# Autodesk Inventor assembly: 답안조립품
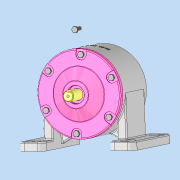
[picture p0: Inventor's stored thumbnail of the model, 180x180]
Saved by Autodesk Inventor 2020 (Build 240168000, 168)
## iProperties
Created: 2025-12
Part Number: 답안조립품
Document SubType Name: Weldment
Designer: PC2-06
Weld Material: Welded Aluminum-6061
Author: PC2-06
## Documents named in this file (16)
- C:\Users\PC2-06\Desktop\751203V1020\답안조립품.iam
- C:\Users\PC2-06\Desktop\751203V1020\본체.ipt
- C:\Users\PC2-06\Desktop\751203V1020\깊은 홈 볼 베어링 6004.ipt
- C:\Users\PC2-06\Desktop\751203V1020\기어 축.ipt
- C:\Users\PC2-06\Desktop\751203V1020\C형 멈춤링 구멍용 42.ipt
- C:\Users\PC2-06\Desktop\751203V1020\칼라 1.ipt
- C:\Users\PC2-06\Desktop\751203V1020\평행 키 6x6x16.ipt
- C:\Users\PC2-06\Desktop\751203V1020\구동 기어.ipt
- C:\Users\PC2-06\Desktop\751203V1020\엔드 캡.ipt
- C:\Users\PC2-06\Desktop\751203V1020\6각 구멍붙이 볼트 M4x10.ipt
- C:\Users\PC2-06\Desktop\751203V1020\출력 축.ipt
- C:\Users\PC2-06\Desktop\751203V1020\종동 기어.ipt
- C:\Users\PC2-06\Desktop\751203V1020\칼라 2.ipt
- C:\Users\PC2-06\Desktop\751203V1020\커버.ipt
- C:\Users\PC2-06\Desktop\751203V1020\깊은 홈 볼 베어링 6005.ipt
- C:\Users\PC2-06\Desktop\751203V1020\6각 머리 볼트 M8x20.ipt
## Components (10 placed, 4 different names)
1. C형 멈춤링 구멍용 42:1
2. 구동 기어:1
3. 6각 구멍붙이 볼트 M4x10:1
4. 6각 머리 볼트 M8x20:6
5. 6각 머리 볼트 M8x20:7
6. 6각 머리 볼트 M8x20:8
7. 6각 머리 볼트 M8x20:9
8. 6각 머리 볼트 M8x20:10
9. 6각 머리 볼트 M8x20:11
10. 6각 머리 볼트 M8x20:12
